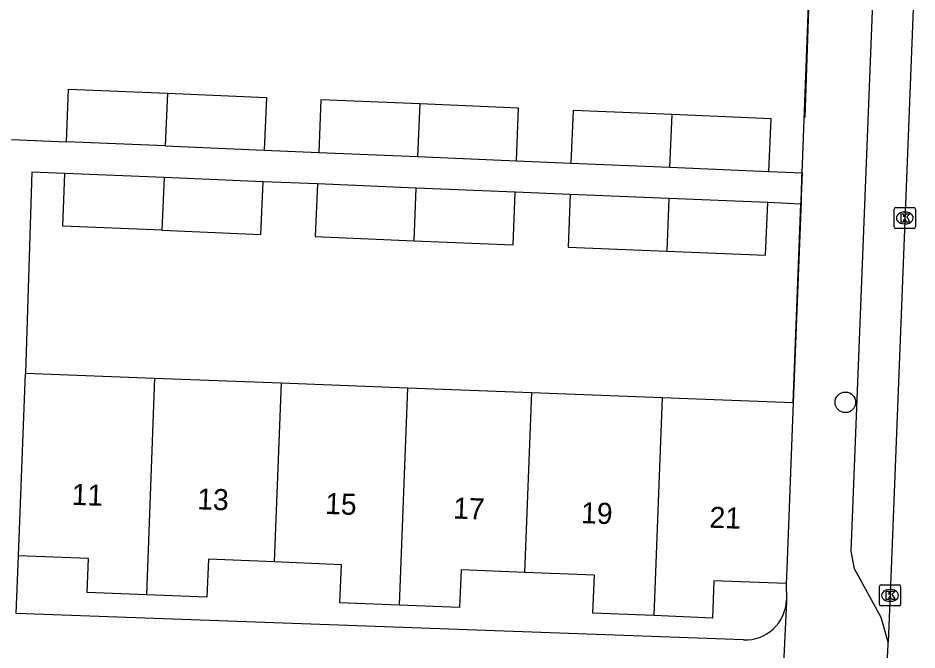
# Model space of a CAD drawing. Extents: x 161355 to 162026, y 386504 to 387459.
# Drawn here: x 161543.02 to 161585.66, y 386996.14 to 387026.14 of the extents above; entities that cross this region are included whole.
import ezdxf

# ---------------------------------------------------------------- set-up
doc = ezdxf.new("R2010")
doc.units = 0
for name, color, linetype in [('IMGEO_Boom', 7, 'Continuous'), ('IMGEO_Kolk', 7, 'Continuous'), ('IMGEO_Muur', 7, 'Continuous'), ('IMGEO_Pand', 7, 'Continuous'), ('IMGEO_Pand_nummerreeks', 7, 'Continuous'), ('IMGEO_Rijbaan_lokaal_open', 7, 'Continuous'), ('IMGEO_Voetpad_open', 7, 'Continuous')]:
    doc.layers.add(name, color=color, linetype=linetype)

msp = doc.modelspace()

# ---------------------------------------------------------------- linework, layer by layer
at = {"layer": 'IMGEO_Boom'}
msp.add_circle((161582.263, 387007.897), 0.489, dxfattribs=at)
at = {"layer": 'IMGEO_Kolk'}
for p, q in [((161584.583, 387016.219), (161584.583, 387017.071)), ((161584.658, 387017.145), (161585.51, 387017.145)), ((161585.071, 387016.925), (161585.096, 387016.925)), ((161585.584, 387017.071), (161585.584, 387016.219)), ((161585.51, 387016.145), (161584.658, 387016.145)), ((161585.094, 387016.365), (161585.069, 387016.365)), ((161583.881, 386998.308), (161583.881, 386999.16)), ((161583.956, 386999.234), (161584.808, 386999.234)), ((161584.369, 386999.014), (161584.394, 386999.014)), ((161584.882, 386999.16), (161584.882, 386998.308)), ((161584.808, 386998.234), (161583.956, 386998.234)), ((161584.392, 386998.454), (161584.367, 386998.454))]:
    msp.add_line(p, q, dxfattribs=at)
for points in [[(161584.583, 387016.219), (161584.583, 387017.071)], [(161584.658, 387017.145), (161585.51, 387017.145)], [(161584.904, 387016.845), (161585.027, 387016.845), (161585.027, 387016.694), (161585.157, 387016.845), (161585.321, 387016.845), (161585.175, 387016.694), (161585.328, 387016.445), (161585.176, 387016.445), (161585.091, 387016.609), (161585.027, 387016.542), (161585.027, 387016.445), (161584.904, 387016.445), (161584.904, 387016.845)], [(161585.584, 387017.071), (161585.584, 387016.219)], [(161585.51, 387016.145), (161584.658, 387016.145)], [(161583.881, 386998.308), (161583.881, 386999.16)], [(161583.956, 386999.234), (161584.808, 386999.234)], [(161584.202, 386998.934), (161584.325, 386998.934), (161584.325, 386998.783), (161584.455, 386998.934), (161584.619, 386998.934), (161584.473, 386998.783), (161584.626, 386998.534), (161584.474, 386998.534), (161584.389, 386998.698), (161584.325, 386998.631), (161584.325, 386998.534), (161584.202, 386998.534), (161584.202, 386998.934)], [(161584.882, 386999.16), (161584.882, 386998.308)], [(161584.808, 386998.234), (161583.956, 386998.234)]]:
    msp.add_lwpolyline(points, dxfattribs=at)
for centre, start, end in [((161584.66, 387017.069), 91.552, 178.448), ((161584.66, 387017.069), 91.552, 178.448), ((161585.508, 387017.069), 1.552, 88.448), ((161585.508, 387017.069), 1.552, 88.448), ((161584.66, 387016.221), 181.552, 268.448), ((161584.66, 387016.221), 181.552, 268.448), ((161585.508, 387016.221), 271.552, 358.448), ((161585.508, 387016.221), 271.552, 358.448), ((161583.958, 386999.158), 91.552, 178.448), ((161583.958, 386999.158), 91.552, 178.448), ((161584.806, 386999.158), 1.552, 88.448), ((161584.806, 386999.158), 1.552, 88.448), ((161583.958, 386998.31), 181.552, 268.448), ((161583.958, 386998.31), 181.552, 268.448), ((161584.806, 386998.31), 271.552, 358.448), ((161584.806, 386998.31), 271.552, 358.448)]:
    msp.add_arc(centre, 0.0765, start, end, dxfattribs=at)
for centre, major_axis, ratio, start_param, end_param in [((161585.07, 387016.645), (-0.387, 0.002), 0.722429, 4.712389, 7.853982), ((161585.095, 387016.645), (-0.39, 0.002), 0.717154, 1.570796, 4.712389), ((161584.368, 386998.734), (-0.387, 0.002), 0.722429, 4.712389, 7.853982), ((161584.393, 386998.734), (-0.39, 0.002), 0.717154, 1.570796, 4.712389)]:
    msp.add_ellipse(centre, major_axis=major_axis, ratio=ratio, start_param=start_param, end_param=end_param, dxfattribs=at)
at = {"layer": 'IMGEO_Muur'}
for points in [[(161580.584, 387028.433), (161580.344, 387021.419)], [(161580.16, 387017.436), (161580.218, 387018.952)], [(161580.16, 387017.436), (161579.791, 387007.89)]]:
    msp.add_lwpolyline(points, dxfattribs=at)
at = {"layer": 'IMGEO_Pand'}
for points in [[(161545.309, 387020.263), (161545.415, 387022.761), (161550.108, 387022.563)], [(161550.108, 387022.563), (161550.003, 387020.066)], [(161550.108, 387022.563), (161554.804, 387022.365), (161554.699, 387019.867)], [(161562.075, 387022.059), (161557.387, 387022.256), (161557.282, 387019.758)], [(161562.075, 387022.059), (161561.97, 387019.561)], [(161566.656, 387019.363), (161566.761, 387021.861), (161562.075, 387022.059)], [(161574.04, 387021.554), (161569.344, 387021.752), (161569.239, 387019.254)], [(161573.935, 387019.056), (161574.04, 387021.554)], [(161578.631, 387018.858), (161578.736, 387021.356), (161574.04, 387021.554)], [(161550.003, 387020.066), (161545.309, 387020.263)], [(161550.003, 387020.066), (161554.699, 387019.867)], [(161557.282, 387019.758), (161561.97, 387019.561)], [(161561.97, 387019.561), (161566.656, 387019.363)], [(161569.239, 387019.254), (161573.935, 387019.056)], [(161573.935, 387019.056), (161578.631, 387018.858)], [(161549.839, 387016.063), (161545.136, 387016.258), (161545.24, 387018.756)], [(161549.943, 387018.561), (161545.24, 387018.756)], [(161549.943, 387018.561), (161549.839, 387016.063)], [(161554.639, 387018.366), (161549.943, 387018.561)], [(161549.839, 387016.063), (161554.535, 387015.868), (161554.639, 387018.366)], [(161557.218, 387018.259), (161557.115, 387015.761), (161561.806, 387015.566)], [(161561.91, 387018.064), (161557.218, 387018.259)], [(161561.806, 387015.566), (161561.91, 387018.064)], [(161561.806, 387015.566), (161566.502, 387015.371), (161566.606, 387017.869)], [(161566.606, 387017.869), (161561.91, 387018.064)], [(161569.215, 387017.761), (161569.112, 387015.263), (161573.791, 387015.069)], [(161573.895, 387017.566), (161569.215, 387017.761)], [(161573.895, 387017.566), (161573.791, 387015.069)], [(161573.791, 387015.069), (161578.477, 387014.874), (161578.581, 387017.372)], [(161578.581, 387017.372), (161573.895, 387017.566)], [(161543.047, 387000.603), (161543.379, 387009.281)], [(161543.379, 387009.281), (161549.495, 387009.047)], [(161549.495, 387009.047), (161549.104, 386998.762)], [(161549.495, 387009.047), (161555.493, 387008.818)], [(161555.493, 387008.818), (161555.171, 387000.319)], [(161555.493, 387008.818), (161561.498, 387008.589)], [(161561.498, 387008.589), (161561.105, 386998.265)], [(161561.498, 387008.589), (161567.39, 387008.364)], [(161567.065, 386999.825), (161567.39, 387008.364)], [(161567.39, 387008.364), (161573.572, 387008.128)], [(161573.572, 387008.128), (161573.179, 386997.773)], [(161573.572, 387008.128), (161574.795, 387008.081), (161579.791, 387007.89)], [(161579.791, 387007.89), (161579.49, 387000), (161579.463, 386999.295)], [(161549.104, 386998.762), (161546.29, 386998.878), (161546.359, 387000.484), (161543.047, 387000.603)], [(161555.171, 387000.319), (161552.047, 387000.45), (161551.977, 386998.644), (161549.104, 386998.762)], [(161561.105, 386998.265), (161558.29, 386998.377), (161558.365, 387000.185), (161555.171, 387000.319)], [(161567.065, 386999.825), (161564.044, 386999.947), (161563.964, 386998.151), (161561.105, 386998.265)], [(161573.179, 386997.773), (161570.282, 386997.896), (161570.357, 386999.691), (161567.065, 386999.825)], [(161579.463, 386999.295), (161576.029, 386999.418), (161575.966, 386997.654), (161573.179, 386997.773)]]:
    msp.add_lwpolyline(points, dxfattribs=at)
at = {"layer": 'IMGEO_Rijbaan_lokaal_open'}
for points in [[(161585.857, 387036.247), (161584.43, 387000), (161584.293, 386996.516)], [(161584.008, 386990.687), (161584.289, 386996.414), (161584.293, 386996.516)]]:
    msp.add_lwpolyline(points, dxfattribs=at)
at = {"layer": 'IMGEO_Voetpad_open'}
for points in [[(161584.293, 386996.516), (161583.966, 386997.683), (161582.692, 387000), (161582.545, 387000.839), (161583.808, 387032.906)], [(161580.21, 387018.791), (161580.584, 387028.433)], [(161542.712, 387020.373), (161545.309, 387020.263)], [(161554.699, 387019.867), (161557.282, 387019.758)], [(161566.656, 387019.363), (161569.239, 387019.254)], [(161545.24, 387018.756), (161543.675, 387018.821), (161543.379, 387009.281)], [(161578.631, 387018.858), (161580.21, 387018.791)], [(161580.21, 387018.791), (161580.155, 387017.307)], [(161557.218, 387018.259), (161554.639, 387018.366)], [(161569.215, 387017.761), (161566.606, 387017.869)], [(161580.155, 387017.307), (161578.581, 387017.372)], [(161579.791, 387007.89), (161580.155, 387017.307)], [(161542.927, 386997.868), (161543.047, 387000.603)], [(161579.463, 386999.295), (161579.468, 386998.517)], [(161579.468, 386998.517), (161579.473, 386998.451), (161579.237, 386993.49)], [(161577.435, 386996.617), (161542.927, 386997.868)]]:
    msp.add_lwpolyline(points, dxfattribs=at)
msp.add_arc((161577.511, 386998.573), 1.958, 267.768, 358.3584, dxfattribs=at)

# ---------------------------------------------------------------- texts
at = {"layer": 'IMGEO_Pand_nummerreeks'}
for s, p in [('11', (161545.552, 387003.034)), ('13', (161551.507, 387002.82)), ('15', (161557.576, 387002.602)), ('17', (161563.646, 387002.384)), ('19', (161569.715, 387002.166)), ('21', (161575.806, 387001.948))]:
    msp.add_text(s, height=1, rotation=357.9429, dxfattribs=at).set_placement(p)

doc.saveas('drawing.dxf')
